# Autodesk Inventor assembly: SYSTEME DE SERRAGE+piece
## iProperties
Shininess: 41.0
Angle Display Precision: 2
Document Length Units: 11269
Document Angle Units: 11279
Document Time Units: 11290
Document Mass Units: 11283
Document Length Units Precision: 3
Document Angle Units Precision: 2
Part Number: SYSTEME DE SERRAGE+piece
Document SubType Name: Assembly
Density: 0.0
Volumn: 0.0
Area: 0.0
PropertySet Name: Model Information
Control State: 0
Master: False
Checked Out: False
